// Mitsubishi GX Works2 project: 实例训练（码垛）（王)   PLC: FX3U/FX3UC

PROGRAM MAIN
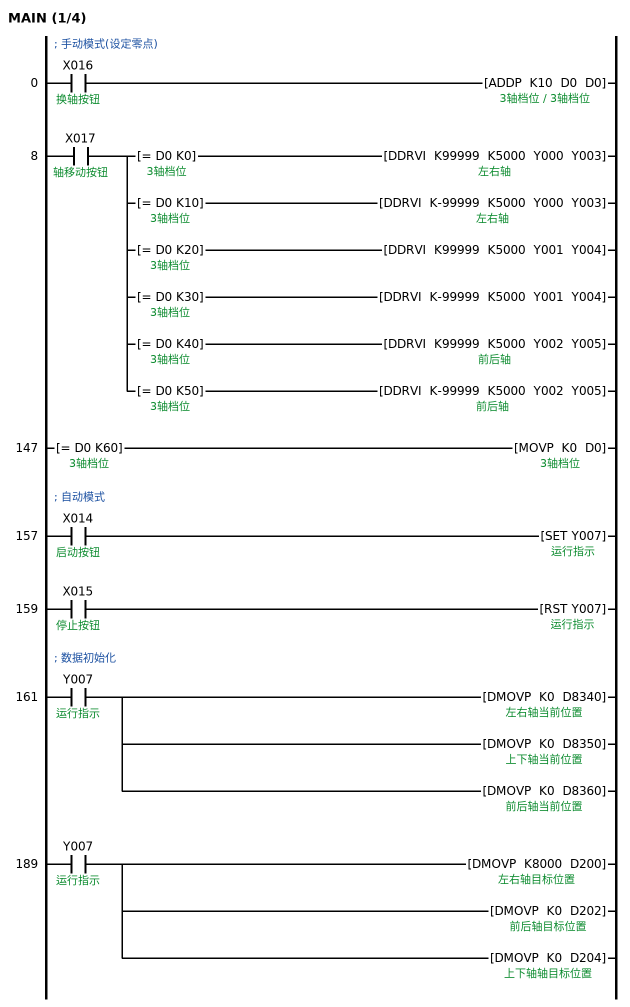
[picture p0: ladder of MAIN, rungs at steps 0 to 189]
; 手动模式(设定零点)
0     LD      X016  ; 换轴按钮
      ADDP    K10 D0 D0  ; 3轴档位
8     LD      X017  ; 轴移动按钮
      MPS
      AND=    D0 K0  ; 3轴档位
      DDRVI   K99999 K5000 Y000 Y003  ; 左右轴
        [note] Y0轴左移
      MRD
      AND=    D0 K10  ; 3轴档位
      DDRVI   K-99999 K5000 Y000 Y003
        [note] Y0轴右移
      MRD
      AND=    D0 K20  ; 3轴档位
      DDRVI   K99999 K5000 Y001 Y004
        [note] Y1轴上移
      MRD
      AND=    D0 K30  ; 3轴档位
      DDRVI   K-99999 K5000 Y001 Y004
        [note] Y1轴下移
      MRD
      AND=    D0 K40  ; 3轴档位
      DDRVI   K99999 K5000 Y002 Y005  ; 前后轴
        [note] Y2轴前移
      MPP
      AND=    D0 K50  ; 3轴档位
      DDRVI   K-99999 K5000 Y002 Y005
        [note] Y2轴后移
147   LD=     D0 K60  ; 3轴档位
      MOVP    K0 D0
; 自动模式
157   LD      X014  ; 启动按钮
      SET     Y007  ; 运行指示
159   LD      X015  ; 停止按钮
      RST     Y007  ; 运行指示
; 数据初始化
161   LD      Y007  ; 运行指示
      DMOVP   K0 D8340  ; 左右轴当前位置
        [note] 三轴数据归零
      DMOVP   K0 D8350  ; 上下轴当前位置
      DMOVP   K0 D8360  ; 前后轴当前位置
189   LD      Y007  ; 运行指示
      DMOVP   K8000 D200  ; 左右轴目标位置
      DMOVP   K0 D202  ; 前后轴目标位置
      DMOVP   K0 D204  ; 上下轴轴目标位置
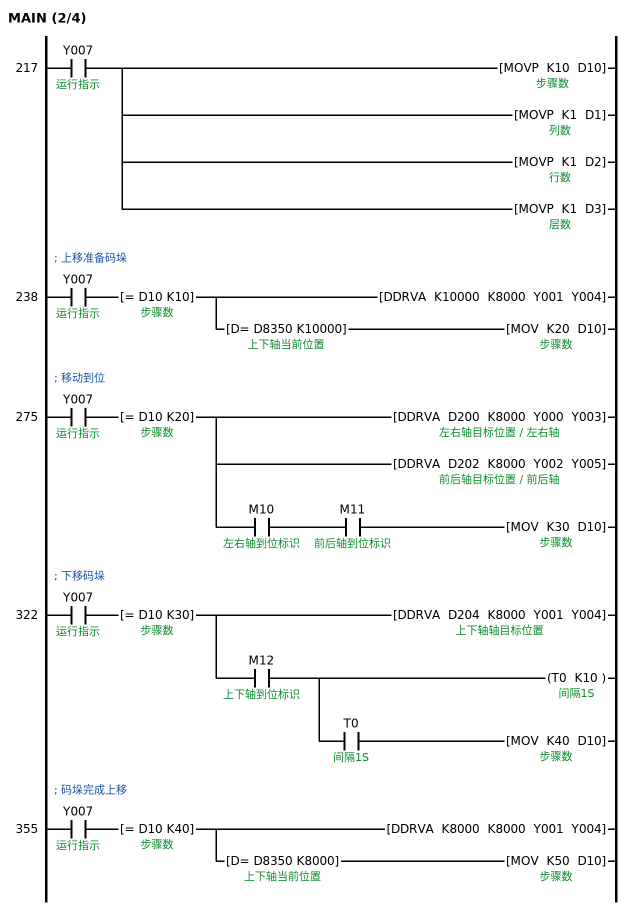
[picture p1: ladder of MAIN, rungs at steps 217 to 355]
217   LD      Y007  ; 运行指示
      MOVP    K10 D10  ; 步骤数
      MOVP    K1 D1  ; 列数
      MOVP    K1 D2  ; 行数
      MOVP    K1 D3  ; 层数
; 上移准备码垛
238   LD      Y007  ; 运行指示
      AND=    D10 K10  ; 步骤数
      DDRVA   K10000 K8000 Y001 Y004
      ANDD=   D8350 K10000  ; 上下轴当前位置
      MOV     K20 D10
; 移动到位
275   LD      Y007  ; 运行指示
      AND=    D10 K20  ; 步骤数
      DDRVA   D200 K8000 Y000 Y003
      DDRVA   D202 K8000 Y002 Y005
      AND     M10  ; 左右轴到位标识
      AND     M11  ; 前后轴到位标识
      MOV     K30 D10
; 下移码垛
322   LD      Y007  ; 运行指示
      AND=    D10 K30  ; 步骤数
      DDRVA   D204 K8000 Y001 Y004
      AND     M12  ; 上下轴到位标识
      OUT     T0 K10  ; 间隔1S
        [note] 放货完成等待1S
      AND     T0  ; 间隔1S
      MOV     K40 D10
; 码垛完成上移
355   LD      Y007  ; 运行指示
      AND=    D10 K40  ; 步骤数
      DDRVA   K8000 K8000 Y001 Y004
      ANDD=   D8350 K8000  ; 上下轴当前位置
      MOV     K50 D10
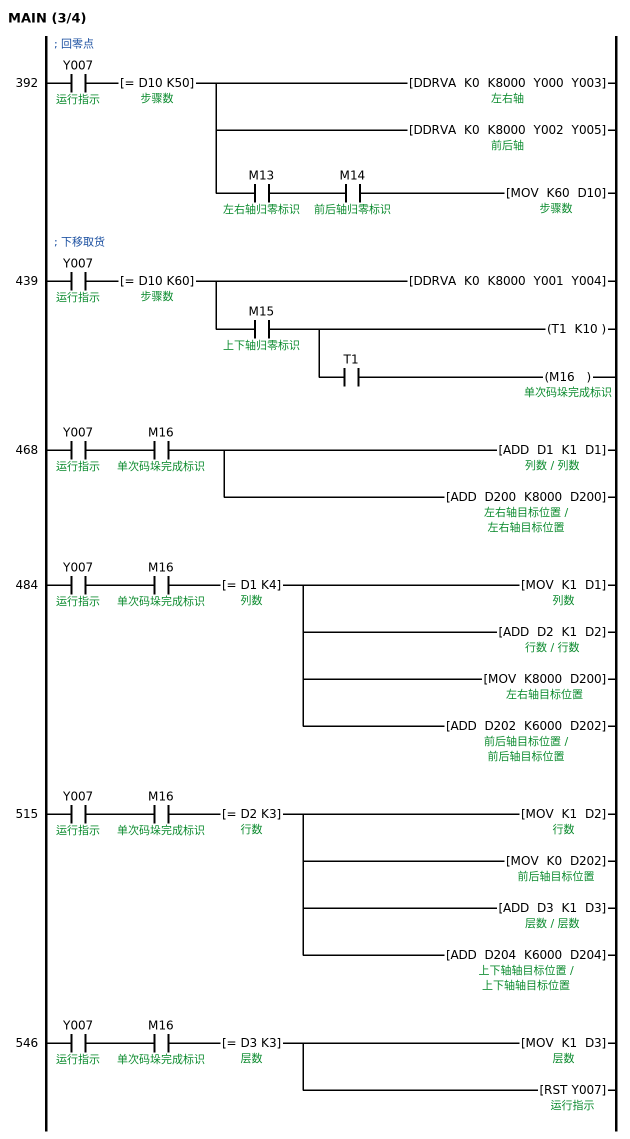
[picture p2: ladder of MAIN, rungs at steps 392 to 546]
; 回零点
392   LD      Y007  ; 运行指示
      AND=    D10 K50  ; 步骤数
      DDRVA   K0 K8000 Y000 Y003
      DDRVA   K0 K8000 Y002 Y005
      AND     M13  ; 左右轴归零标识
      AND     M14  ; 前后轴归零标识
      MOV     K60 D10
; 下移取货
439   LD      Y007  ; 运行指示
      AND=    D10 K60  ; 步骤数
      DDRVA   K0 K8000 Y001 Y004
      AND     M15  ; 上下轴归零标识
      OUT     T1 K10
      AND     T1
      OUT     M16  ; 单次码垛完成标识
468   LD      Y007  ; 运行指示
      AND     M16  ; 单次码垛完成标识
      ADD     D1 K1 D1
      ADD     D200 K8000 D200
484   LD      Y007  ; 运行指示
      AND     M16  ; 单次码垛完成标识
      AND=    D1 K4  ; 列数
      MOV     K1 D1
      ADD     D2 K1 D2
      MOV     K8000 D200
      ADD     D202 K6000 D202
515   LD      Y007  ; 运行指示
      AND     M16  ; 单次码垛完成标识
      AND=    D2 K3  ; 行数
      MOV     K1 D2
      MOV     K0 D202
      ADD     D3 K1 D3
      ADD     D204 K6000 D204
546   LD      Y007  ; 运行指示
      AND     M16  ; 单次码垛完成标识
      AND=    D3 K3  ; 层数
      MOV     K1 D3
      RST     Y007  ; 运行指示
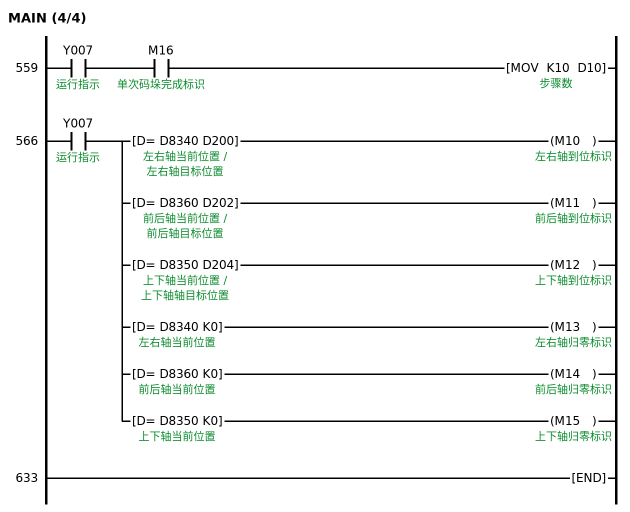
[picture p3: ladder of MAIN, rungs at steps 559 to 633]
559   LD      Y007  ; 运行指示
      AND     M16  ; 单次码垛完成标识
      MOV     K10 D10
566   LD      Y007  ; 运行指示
      MPS
      ANDD=   D8340 D200  ; 左右轴当前位置 / 左右轴目标位置
      OUT     M10  ; 左右轴到位标识
      MRD
      ANDD=   D8360 D202  ; 前后轴当前位置 / 前后轴目标位置
      OUT     M11  ; 前后轴到位标识
      MRD
      ANDD=   D8350 D204  ; 上下轴当前位置 / 上下轴轴目标位置
      OUT     M12  ; 上下轴到位标识
      MRD
      ANDD=   D8340 K0  ; 左右轴当前位置
      OUT     M13  ; 左右轴归零标识
      MRD
      ANDD=   D8360 K0  ; 前后轴当前位置
      OUT     M14  ; 前后轴归零标识
      MPP
      ANDD=   D8350 K0  ; 上下轴当前位置
      OUT     M15  ; 上下轴归零标识
633   END
END_PROGRAM
